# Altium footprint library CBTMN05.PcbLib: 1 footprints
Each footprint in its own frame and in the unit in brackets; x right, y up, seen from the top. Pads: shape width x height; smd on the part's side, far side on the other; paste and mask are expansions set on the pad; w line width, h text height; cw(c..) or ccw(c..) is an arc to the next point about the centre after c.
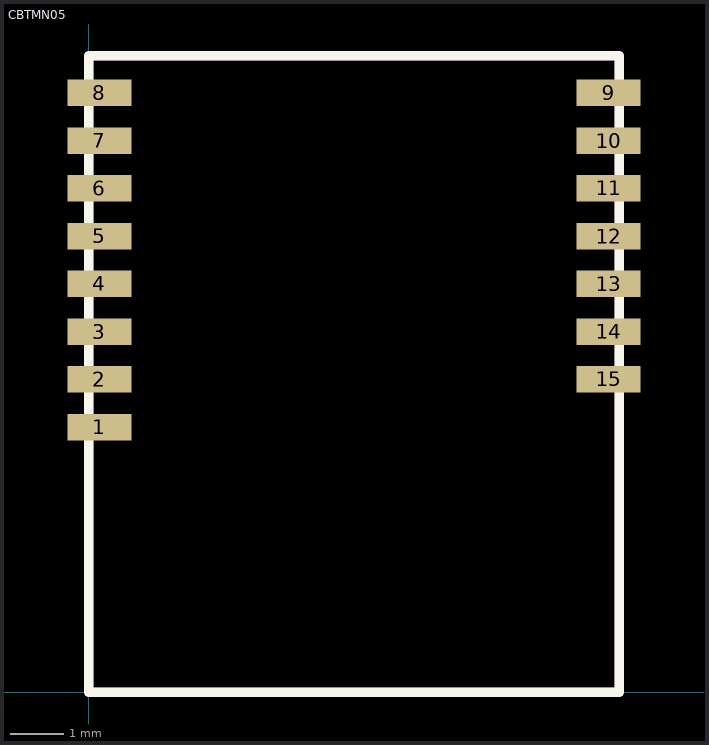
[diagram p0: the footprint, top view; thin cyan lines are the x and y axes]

## CBTMN05 [mm]
pads (15):
  rect 1.2x0.5 smd: 1(0.2,5) 2(0.2,5.9) 3(0.2,6.8) 4(0.2,7.7) 5(0.2,8.6) 6(0.2,9.5) 7(0.2,10.4) 8(0.2,11.3) 9(9.8,11.3) 10(9.8,10.4) 11(9.8,9.5) 12(9.8,8.6) 13(9.8,7.7) 14(9.8,6.8) 15(9.8,5.9)
L26-Silk Screen Top (Multiple PADS layers...):
  lines w0.178: 0,0 10,0 10,12 0,12 0,0
L15 (Multiple PADS layers...):
  region: 0,4.8 0.6,4.8 0.6,5.2 0,5.2
  region: 0,5.7 0.6,5.7 0.6,6.1 0,6.1
  region: 0,6.6 0.6,6.6 0.6,7 0,7
  region: 0,7.5 0.6,7.5 0.6,7.9 0,7.9
  region: 0,8.4 0.6,8.4 0.6,8.8 0,8.8
  region: 0,9.3 0.6,9.3 0.6,9.7 0,9.7
  region: 0,10.2 0.6,10.2 0.6,10.6 0,10.6
  region: 0,11.1 0.6,11.1 0.6,11.5 0,11.5
  region: 9.4,11.1 10,11.1 10,11.5 9.4,11.5
  region: 9.4,10.2 10,10.2 10,10.6 9.4,10.6
  region: 9.4,9.3 10,9.3 10,9.7 9.4,9.7
  region: 9.4,8.4 10,8.4 10,8.8 9.4,8.8
  region: 9.4,7.5 10,7.5 10,7.9 9.4,7.9
  region: 9.4,6.6 10,6.6 10,7 9.4,7
  region: 9.4,5.7 10,5.7 10,6.1 9.4,6.1
  lines w0.178: 0,0 10,0 10,12 0,12 0,0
